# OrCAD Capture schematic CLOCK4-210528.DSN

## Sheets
1 ArduinoNano30: size A3
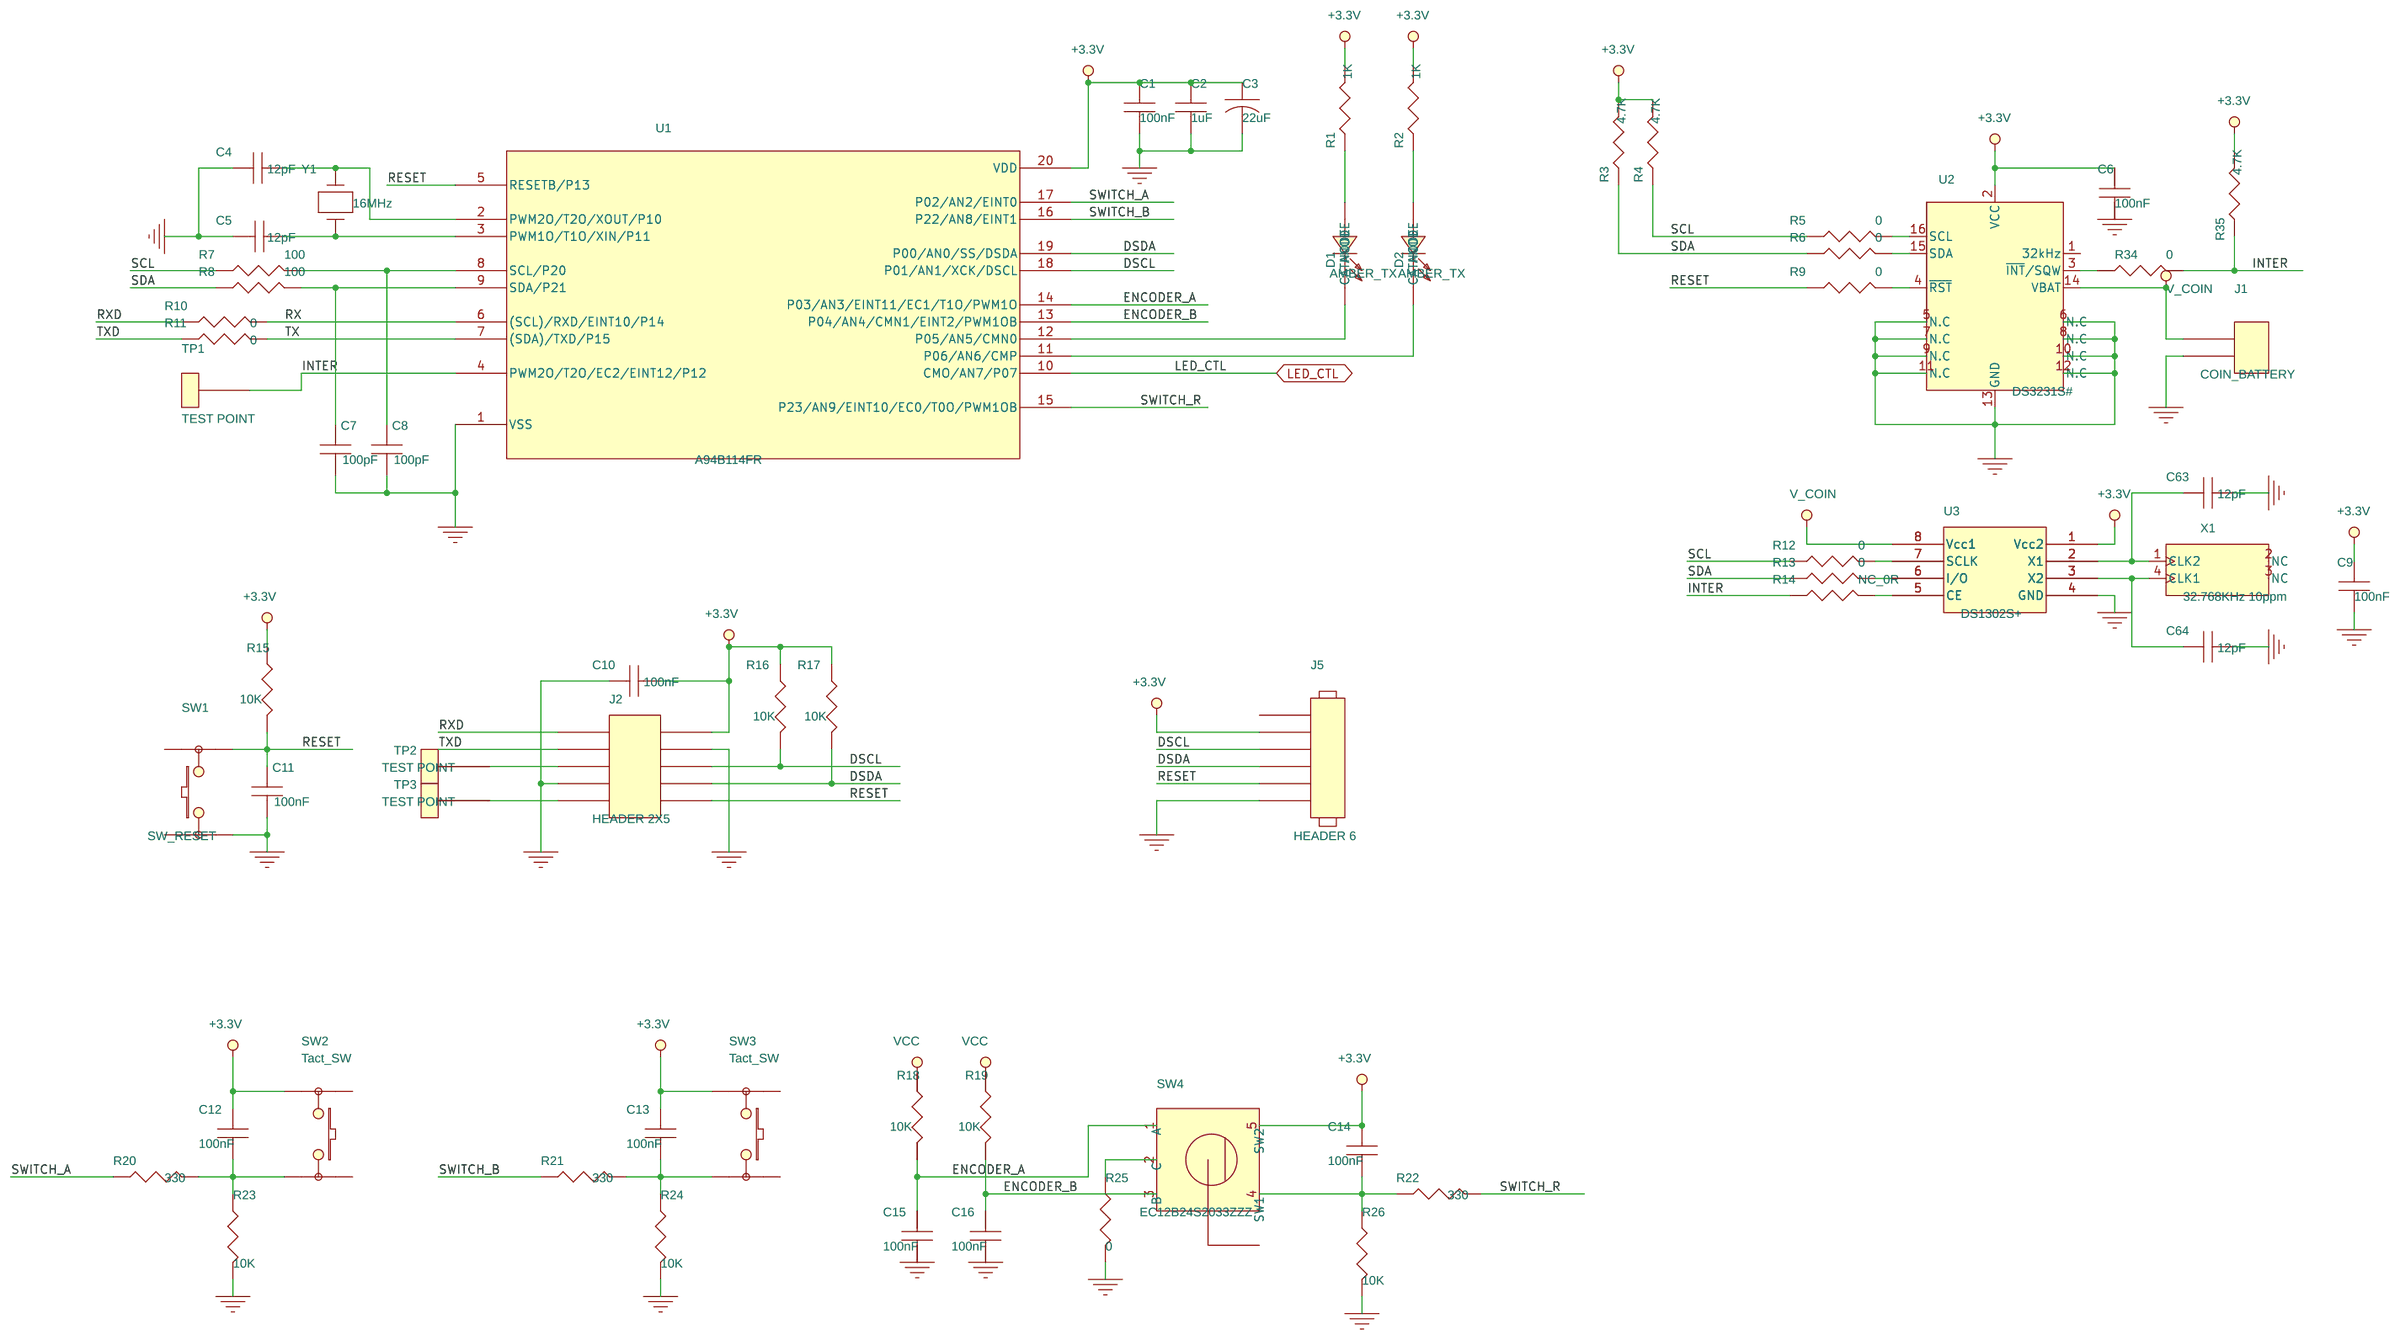
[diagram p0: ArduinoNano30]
2 CLOCK: size A3
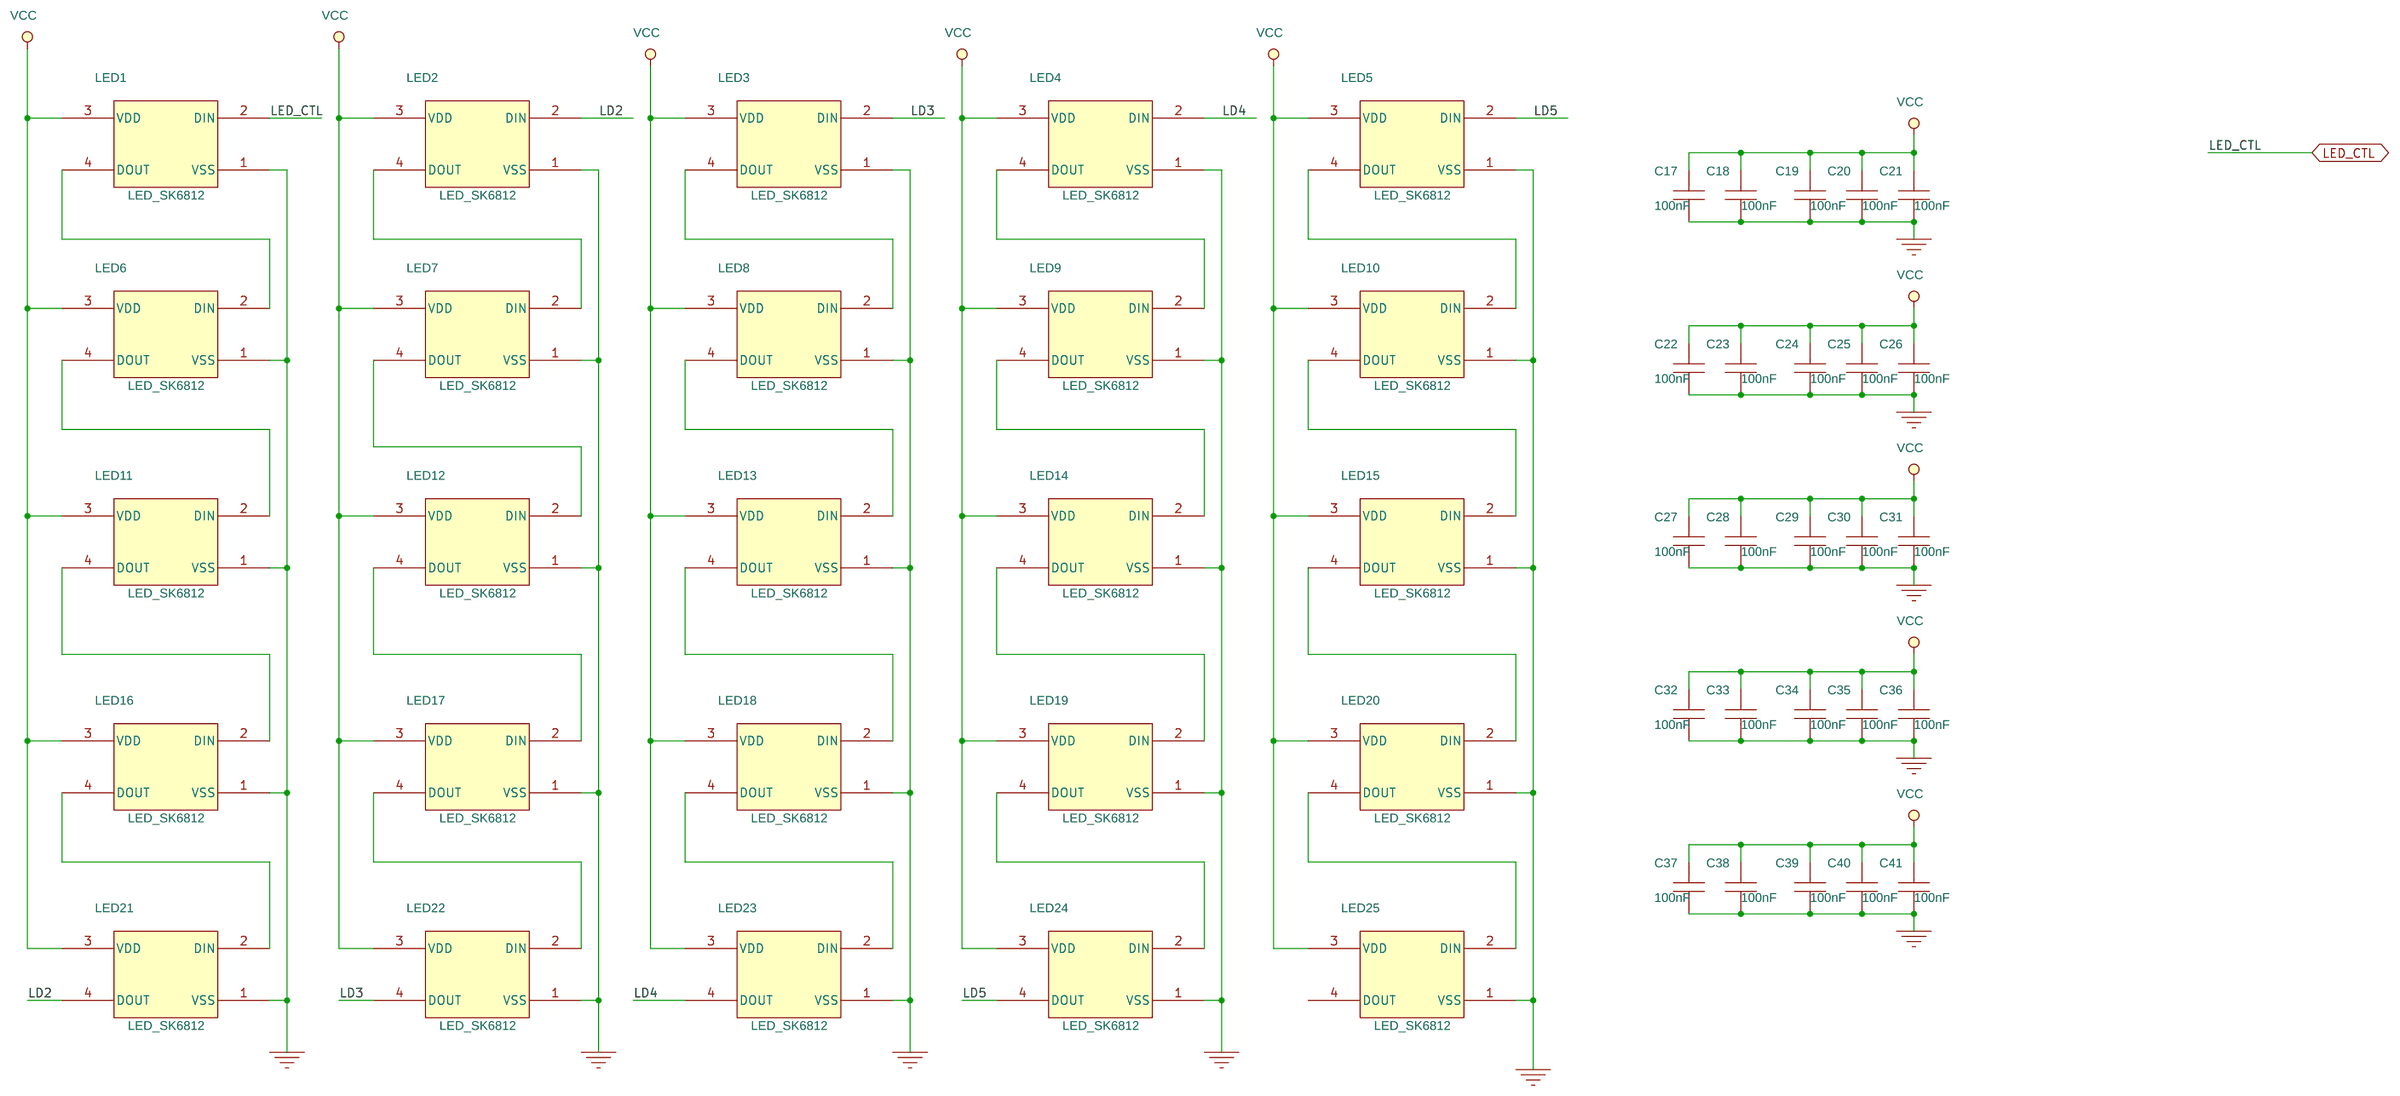
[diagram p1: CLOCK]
3 POWER: size A3
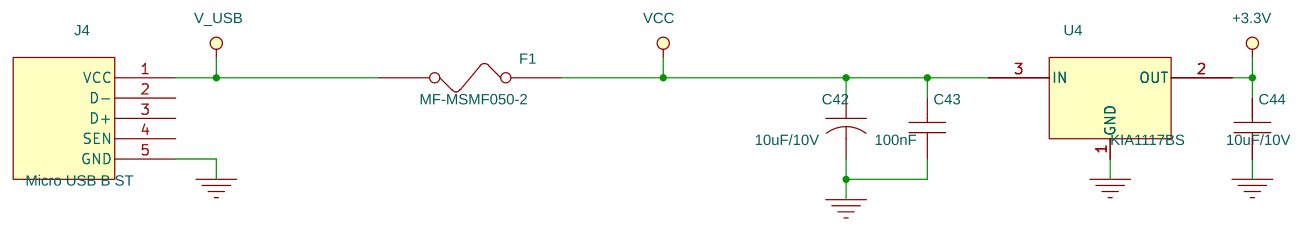
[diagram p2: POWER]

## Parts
sheet ArduinoNano30
C1  100nF  [C1608]
C2  1uF  [C2012]
C3  22uF  [C3216]
C4  12pF  [C1608]
C5  12pF  [C1608]
C6  100nF  [C1608]
C7  100pF  [C1608]
C8  100pF  [C1608]
C9  100nF  [C1608]
C10  100nF  [C1608]
C11  100nF  [C1608]
C12  100nF  [C1608]
C13  100nF  [C1608]
C14  100nF  [C1608]
C15  100nF  [C1608]
C16  100nF  [C1608]
C63  12pF  [C1608]
C64  12pF  [C1608]
D1  AMBER_TX  [LED1608]
D2  AMBER_TX  [LED1608]
J1  COIN_BATTERY  [B681220]
J2  HEADER 2X5  [BOXHEADER-10X2-2.54(SMD)]
J5  HEADER 6
R1  1K  [R1608]
R2  1K  [R1608]
R3  4.7K  [R1608]
R4  4.7K  [R1608]
R5  0  [R1608]
R6  0  [R1608]
R7  100  [R1608]
R8  100  [R1608]
R9  0  [R1608]
R10  0  [R1608]
R11  0  [R1608]
R12  0  [R1608]
R13  0  [R1608]
R14  NC_0R  [R1608]
R15  10K  [R1608]
R16  10K  [R1608]
R17  10K  [R1608]
R18  10K  [R1608]
R19  10K  [R1608]
R20  330  [R1608]
R21  330  [R1608]
R22  330  [R1608]
R23  10K  [R1608]
R24  10K  [R1608]
R25  0  [R1608]
R26  10K  [R1608]
R34  0  [R1608]
R35  4.7K  [R1608]
SW1  SW_RESET  [TACT-1102S]
SW2  Tact_SW  [TACT-1102S]
SW3  Tact_SW  [TACT-1102S]
SW4  EC12B24S2033ZZZ  [EC12B24S2033ZZZ]
TP1  TEST POINT  [TP1.5-SMD-CIR]
TP2  TEST POINT  [TP1.5-SMD-CIR]
TP3  TEST POINT  [TP1.5-SMD-CIR]
U1  A94B114FR  [A94B114FR/TSSOP20]
U2  DS3231S#  [DS3231S/WSOIC16]
U3  DS1302S+  [DS1302S+/WSOC8]
X1  32.768KHz 10ppm  [CS-306]
Y1  16MHz  [XTAL-3225]
sheet CLOCK
C17  100nF  [C1608]
C18  100nF  [C1608]
C19  100nF  [C1608]
C20  100nF  [C1608]
C21  100nF  [C1608]
C22  100nF  [C1608]
C23  100nF  [C1608]
C24  100nF  [C1608]
C25  100nF  [C1608]
C26  100nF  [C1608]
C27  100nF  [C1608]
C28  100nF  [C1608]
C29  100nF  [C1608]
C30  100nF  [C1608]
C31  100nF  [C1608]
C32  100nF  [C1608]
C33  100nF  [C1608]
C34  100nF  [C1608]
C35  100nF  [C1608]
C36  100nF  [C1608]
C37  100nF  [C1608]
C38  100nF  [C1608]
C39  100nF  [C1608]
C40  100nF  [C1608]
C41  100nF  [C1608]
LED1  LED_SK6812  [LED-SK6812]
LED2  LED_SK6812  [LED-SK6812]
LED3  LED_SK6812  [LED-SK6812]
LED4  LED_SK6812  [LED-SK6812]
LED5  LED_SK6812  [LED-SK6812]
LED6  LED_SK6812  [LED-SK6812]
LED7  LED_SK6812  [LED-SK6812]
LED8  LED_SK6812  [LED-SK6812]
LED9  LED_SK6812  [LED-SK6812]
LED10  LED_SK6812  [LED-SK6812]
LED11  LED_SK6812  [LED-SK6812]
LED12  LED_SK6812  [LED-SK6812]
LED13  LED_SK6812  [LED-SK6812]
LED14  LED_SK6812  [LED-SK6812]
LED15  LED_SK6812  [LED-SK6812]
LED16  LED_SK6812  [LED-SK6812]
LED17  LED_SK6812  [LED-SK6812]
LED18  LED_SK6812  [LED-SK6812]
LED19  LED_SK6812  [LED-SK6812]
LED20  LED_SK6812  [LED-SK6812]
LED21  LED_SK6812  [LED-SK6812]
LED22  LED_SK6812  [LED-SK6812]
LED23  LED_SK6812  [LED-SK6812]
LED24  LED_SK6812  [LED-SK6812]
LED25  LED_SK6812  [LED-SK6812]
sheet POWER
C42  10uF/10V  [TT-2012]
C43  100nF  [C1608]
C44  10uF/10V  [TT-2012]
F1  MF-MSMF050-2  [MF-MSMF050-2]
J4  Micro USB B ST  [MICRO-USB-ST-A12]
U4  KIA1117BS  [KIA1117BS/SOT-223]

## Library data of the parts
C1 C2 C4-C41 C43 C44 C63 C64 = CAP_NP
C3 C42 = C
D1 D2 = LED_4
J1 = CON2
J2 = CON10A
J5 = HEADER_6
R1-R26 R34 R35 = R
SW1-SW3 = SW_PUSHBUTTON-SPST-2
SW4 = EC12B24S2033ZZZ
TP1-TP3 = TEST_POINT
U1 = A94B114FR
U2 = DS3231
U3 = DS1302
X1 = CS-306
Y1 = CRYSTAL_0
LED1-LED25 = LED_SK6812
F1 = FUSE
J4 = micro_USB
U4 = KIA1117_0

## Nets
+3.3V: C1.1 C2.1 C3.1 C6.1 C9.1 C10.2 C12.1 C13.1 C14.1 C44.1 J2.2 J5.2 R1.1 R2.1 R3.1 R4.1 R15.2 R16.2 R17.2 R18.2 R19.2 R35.1 SW2.2 SW3.2 SW4.5(SW2) U1.20(VDD) U2.2(VCC) U3.1(Vcc2) U4.2(OUT)
GND: C1.2 C2.2 C3.2 C4.1 C5.2 C6.2 C7.2 C8.2 C9.2 C10.1 C11.2 C15.2 C16.2 C17.2 C18.2 C19.2 C20.2 C21.2 C22.2 C23.2 C24.2 C25.2 C26.2 C27.2 C28.2 C29.2 C30.2 C31.2 C32.2 C33.2 C34.2 C35.2 C36.2 C37.2 C38.2 C39.2 C40.2 C41.2 C42.2 C43.2 C44.2 C63.2 C64.2 J1.2 J2.4 J2.7 J4.5(GND) J5.6 LED1.1(VSS) LED2.1(VSS) LED3.1(VSS) LED4.1(VSS) LED5.1(VSS) LED6.1(VSS) LED7.1(VSS) LED8.1(VSS) LED9.1(VSS) LED10.1(VSS) LED11.1(VSS) LED12.1(VSS) LED13.1(VSS) LED14.1(VSS) LED15.1(VSS) LED16.1(VSS) LED17.1(VSS) LED18.1(VSS) LED19.1(VSS) LED20.1(VSS) LED21.1(VSS) LED22.1(VSS) LED23.1(VSS) LED24.1(VSS) LED25.1(VSS) R23.2 R24.2 R25.2 R26.2 SW1.3 U1.1(VSS) U2.5(N.C) U2.6(N.C) U2.7(N.C) U2.8(N.C) U2.9(N.C) U2.10(N.C) U2.11(N.C) U2.12(N.C) U2.13(GND) U3.4(GND) U4.1(GND)
VCC: C17.1 C18.1 C19.1 C20.1 C21.1 C22.1 C23.1 C24.1 C25.1 C26.1 C27.1 C28.1 C29.1 C30.1 C31.1 C32.1 C33.1 C34.1 C35.1 C36.1 C37.1 C38.1 C39.1 C40.1 C41.1 C42.1 C43.1 F1.1 LED1.3(VDD) LED2.3(VDD) LED3.3(VDD) LED4.3(VDD) LED5.3(VDD) LED6.3(VDD) LED7.3(VDD) LED8.3(VDD) LED9.3(VDD) LED10.3(VDD) LED11.3(VDD) LED12.3(VDD) LED13.3(VDD) LED14.3(VDD) LED15.3(VDD) LED16.3(VDD) LED17.3(VDD) LED18.3(VDD) LED19.3(VDD) LED20.3(VDD) LED21.3(VDD) LED22.3(VDD) LED23.3(VDD) LED24.3(VDD) LED25.3(VDD) U4.3(IN)
DSCL: J2.6 J5.3 R16.1 U1.18(P01/AN1/XCK/DSCL)
DSDA: J2.8 J5.4 R17.1 U1.19(P00/AN0/SS/DSDA)
ENCODER_A: C15.1 R18.1 SW4.1(A) U1.14(P03/AN3/EINT11/EC1/T1O/PWM1O)
ENCODER_B: C16.1 R19.1 SW4.3(B) U1.13(P04/AN4/CMN1/EINT2/PWM1OB)
INTER: R14.1 R34.2 R35.2 TP1.1 U1.4(PWM2O/T2O/EC2/EINT12/P12)
LD2: LED2.2(DIN) LED21.4(DOUT)
LD3: LED3.2(DIN) LED22.4(DOUT)
LD4: LED4.2(DIN) LED23.4(DOUT)
LD5: LED5.2(DIN) LED24.4(DOUT)
LED_CTL: LED1.2(DIN) U1.10(CMO/AN7/P07)
RESET: C11.1 J2.10 J5.5 R9.1 R15.1 SW1.2 U1.5(RESETB/P13)
RX: R10.2 U1.6((SCL)/RXD/EINT10/P14)
RXD: J2.1 R10.1
SCL: R4.2 R5.1 R7.1 R12.1
SDA: R3.2 R6.1 R8.1 R13.1
SWITCH_A: R20.1 U1.17(P02/AN2/EINT0)
SWITCH_B: R21.1 U1.16(P22/AN8/EINT1)
SWITCH_R: R22.2 U1.15(P23/AN9/EINT10/EC0/T0O/PWM1OB)
TX: R11.2 U1.7((SDA)/TXD/P15)
TXD: J2.3 R11.1
V_COIN: J1.1 U2.14(VBAT) U3.8(Vcc1)
V_USB: F1.2 J4.1(VCC)
N16369: C5.1 U1.3(PWM1O/T1O/XIN/P11) Y1.1
N16373: C4.2 U1.2(PWM2O/T2O/XOUT/P10) Y1.3
N22466: D1.A(ANODE) R1.2
N22532: D1.C(CATHODE) U1.12(P05/AN5/CMN0)
N41062: LED1.4(DOUT) LED6.2(DIN)
N41074: LED6.4(DOUT) LED11.2(DIN)
N41086: LED11.4(DOUT) LED16.2(DIN)
N41098: LED16.4(DOUT) LED21.2(DIN)
N41110: LED2.4(DOUT) LED7.2(DIN)
N41122: LED7.4(DOUT) LED12.2(DIN)
N41134: LED12.4(DOUT) LED17.2(DIN)
N41146: LED17.4(DOUT) LED22.2(DIN)
N41158: LED3.4(DOUT) LED8.2(DIN)
N41170: LED8.4(DOUT) LED13.2(DIN)
N41182: LED13.4(DOUT) LED18.2(DIN)
N41194: LED18.4(DOUT) LED23.2(DIN)
N41206: LED4.4(DOUT) LED9.2(DIN)
N41218: LED9.4(DOUT) LED14.2(DIN)
N41230: LED14.4(DOUT) LED19.2(DIN)
N41242: LED19.4(DOUT) LED24.2(DIN)
N41254: LED5.4(DOUT) LED10.2(DIN)
N41266: LED10.4(DOUT) LED15.2(DIN)
N41278: LED15.4(DOUT) LED20.2(DIN)
N41290: LED20.4(DOUT) LED25.2(DIN)
N49104: R9.2 U2.4(~{RST})
N87315: R14.2 U3.5(CE)
N87406: R12.2 U3.7(SCLK)
N87410: R13.2 U3.6(I/O)
N87650: R5.2 U2.16(SCL)
N87654: R6.2 U2.15(SDA)
N87914: C63.1 U3.2(X1) X1.1(CLK2)
N87918: C64.1 U3.3(X2) X1.4(CLK1)
N94684: C8.1 R7.2 U1.8(SCL/P20)
N94688: C7.1 R8.2 U1.9(SDA/P21)
N101162: C12.2 R20.2 R23.1 SW2.3
N101178: C13.2 R21.2 R24.1 SW3.3
N104311: C14.2 R22.1 R26.1 SW4.4(SW1)
N110731: R25.1 SW4.2(C)
N138596: J2.5 TP2.1
N138622: J2.9 TP3.1
N139626: D2.A(ANODE) R2.2
N139630: D2.C(CATHODE) U1.11(P06/AN6/CMP)
N163523: R34.1 U2.3(~{INT}/SQW)

Not connected (* = marked no-connect by the designer): J4 2(D-) 3(D+) 4(SEN); J5 1; LED25 4(DOUT); SW1 1 4; SW2 1 4; SW3 1 4; U2 1(32kHz); X1 2(NC) 3(NC)
